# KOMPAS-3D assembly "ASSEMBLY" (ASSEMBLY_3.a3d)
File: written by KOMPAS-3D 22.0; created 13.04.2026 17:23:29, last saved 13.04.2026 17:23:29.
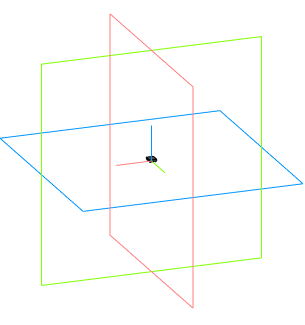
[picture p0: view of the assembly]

Document properties: Автор: Andrey; Полное имя файла: C:\Users\User1\Documents\ASSEMBLY_3.a3d

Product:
- Component [detail]: Array  | qty 1  | source file: Array.m3d
- Component [detail]: Body  | qty 1  | source file: Body_4.m3d
- Part/product: ASSEMBLY

Referenced files in C:\Users\User1\Documents\: Array.m3d, Body_4.m3d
